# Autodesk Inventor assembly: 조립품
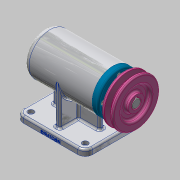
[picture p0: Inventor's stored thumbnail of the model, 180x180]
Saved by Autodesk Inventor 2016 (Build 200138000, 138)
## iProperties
Created: 2020-10
Part Number: 조립품
Material: 일반
Document SubType Name: Assembly
Designer: 605-17
Author: 605-17
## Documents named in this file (12)
- C:\Users\605-17\Desktop\701004V1007\조립품.iam
- C:\Users\605-17\Desktop\701004V1007\본체.ipt
- C:\Users\605-17\Desktop\701004V1007\베어링 6004.ipt
- C:\Users\605-17\Desktop\701004V1007\축.ipt
- C:\Users\605-17\Desktop\701004V1007\어댑터슬리브.ipt
- C:\Users\605-17\Desktop\701004V1007\베어링 51202.ipt
- C:\Users\605-17\Desktop\701004V1007\볼트 M4.ipt
- C:\Users\605-17\Desktop\701004V1007\커버.ipt
- C:\Users\605-17\Desktop\701004V1007\Ű 5 x 5 x 16.ipt
- C:\Users\605-17\Desktop\701004V1007\오일 실.ipt
- C:\Users\605-17\Desktop\701004V1007\V벨트풀리.ipt
- C:\Users\605-17\Desktop\701004V1007\멈춤나사 M3.ipt
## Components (2 placed, 2 different names)
1. Ű 5 x 5 x 16:1 — 플러쉬:1
2. V벨트풀리:1
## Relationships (1: Flush 1)
- 플러쉬:1 [Flush]: Ű 5 x 5 x 16:1
